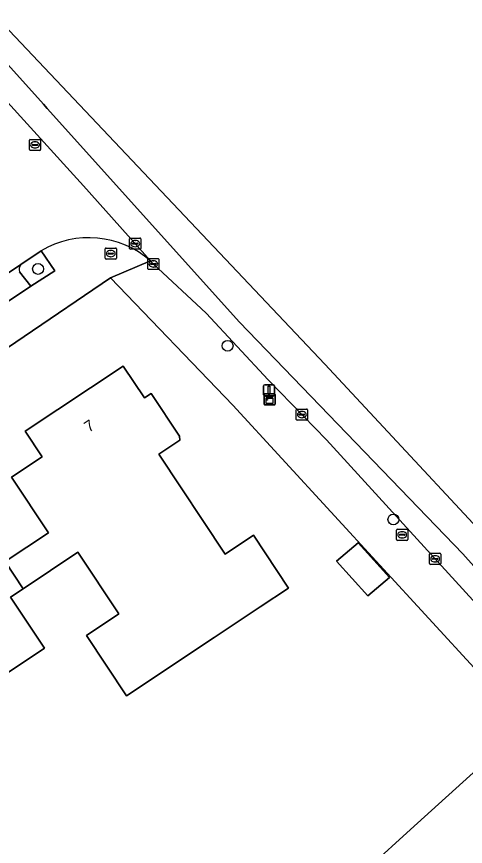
# Model space of a CAD drawing. Extents: x 161347 to 161881, y 382161 to 382804.
# Drawn here: x 161633.8 to 161674.2, y 382587.4 to 382662.1 of the extents above; entities that cross this region are included whole.
import ezdxf

# ---------------------------------------------------------------- set-up
doc = ezdxf.new("R2010")
doc.units = 0
for name, color, linetype in [('IMGEO_Boom', 7, 'Continuous'), ('IMGEO_Brandkraan', 7, 'Continuous'), ('IMGEO_Erf', 7, 'Continuous'), ('IMGEO_Fietspad_gesloten', 7, 'Continuous'), ('IMGEO_Groenvoorziening', 7, 'Continuous'), ('IMGEO_Kast', 7, 'Continuous'), ('IMGEO_Kolk', 7, 'Continuous'), ('IMGEO_Lichtmast', 7, 'Continuous'), ('IMGEO_Muur', 7, 'Continuous'), ('IMGEO_Pand', 7, 'Continuous'), ('IMGEO_Pand_nummerreeks', 7, 'Continuous'), ('IMGEO_Parkeervlak_open', 7, 'Continuous'), ('IMGEO_Rijbaan_lokaal_gesloten', 7, 'Continuous'), ('IMGEO_Rijbaan_lokaal_open', 7, 'Continuous'), ('IMGEO_Rioolput', 7, 'Continuous'), ('IMGEO_Voetpad_open', 7, 'Continuous')]:
    doc.layers.add(name, color=color, linetype=linetype)

msp = doc.modelspace()

# ---------------------------------------------------------------- linework, layer by layer
at = {"layer": 'IMGEO_Boom'}
for centre in [(161635.76, 382639.355), (161652.819, 382632.433), (161667.742, 382616.798)]:
    msp.add_circle(centre, 0.489, dxfattribs=at)
at = {"layer": 'IMGEO_Brandkraan'}
for p, q in [((161641.807, 382640.31), (161641.807, 382641.162)), ((161641.882, 382641.236), (161642.734, 382641.236)), ((161642.066, 382640.73), (161642.066, 382640.742)), ((161642.504, 382640.693), (161642.106, 382640.693)), ((161642.109, 382640.779), (161642.507, 382640.779)), ((161642.295, 382641.016), (161642.32, 382641.016)), ((161642.55, 382640.742), (161642.55, 382640.73)), ((161642.808, 382641.162), (161642.808, 382640.31)), ((161642.734, 382640.236), (161641.882, 382640.236)), ((161642.318, 382640.456), (161642.293, 382640.456))]:
    msp.add_line(p, q, dxfattribs=at)
for points in [[(161641.807, 382640.31), (161641.807, 382641.162)], [(161641.882, 382641.236), (161642.734, 382641.236)], [(161642.808, 382641.162), (161642.808, 382640.31)], [(161642.734, 382640.236), (161641.882, 382640.236)]]:
    msp.add_lwpolyline(points, dxfattribs=at)
for centre, radius, start, end in [((161641.884, 382641.16), 0.0765, 91.55205, 178.44795), ((161641.884, 382641.16), 0.0765, 91.55205, 178.44795), ((161642.106, 382640.739), 0.0403, 85.87752, 175.75265), ((161642.103, 382640.729), 0.0366, 178.93798, 274.71019), ((161642.507, 382640.736), 0.043, 264.86636, 352.45326), ((161642.511, 382640.741), 0.0386, 1.73085, 96.63898), ((161642.732, 382641.16), 0.0765, 1.55205, 88.44795), ((161642.732, 382641.16), 0.0765, 1.55205, 88.44795), ((161641.884, 382640.312), 0.0765, 181.55205, 268.44795), ((161641.884, 382640.312), 0.0765, 181.55205, 268.44795), ((161642.732, 382640.312), 0.0765, 271.55205, 358.44795), ((161642.732, 382640.312), 0.0765, 271.55205, 358.44795)]:
    msp.add_arc(centre, radius, start, end, dxfattribs=at)
for centre, major_axis, ratio, start_param, end_param in [((161642.294, 382640.736), (-0.387, 0.002), 0.722429, 4.712389, 7.853982), ((161642.319, 382640.736), (-0.39, 0.002), 0.717154, 1.570796, 4.712389)]:
    msp.add_ellipse(centre, major_axis=major_axis, ratio=ratio, start_param=start_param, end_param=end_param, dxfattribs=at)
at = {"layer": 'IMGEO_Erf'}
for points in [[(161665.593, 382585.519), (161669.295, 382588.879), (161675.871, 382594.848), (161676.366, 382595.297), (161679.75, 382598.28), (161653.29, 382627.1), (161642.272, 382638.554), (161626.724, 382627.988), (161591.014, 382604.147), (161592.626, 382601.772), (161590.519, 382600.398), (161588.954, 382602.772), (161572.092, 382591.77), (161539.981, 382570.178)], [(161632.808, 382613.004), (161636.704, 382615.596), (161633.373, 382620.601), (161636.145, 382622.446), (161634.617, 382624.742), (161643.428, 382630.605), (161645.338, 382627.735), (161645.942, 382628.137), (161648.492, 382624.305), (161648.516, 382623.924), (161646.628, 382622.668), (161652.605, 382613.685), (161655.144, 382615.375), (161658.302, 382610.63), (161655.763, 382608.94), (161651.601, 382606.171), (161643.724, 382600.93), (161640.118, 382606.349), (161643.044, 382608.296), (161639.351, 382613.846), (161634.428, 382610.57), (161633.287, 382609.811), (161636.354, 382605.203), (161629.995, 382600.972)]]:
    msp.add_lwpolyline(points, dxfattribs=at)
msp.add_lwpolyline([(161662.617, 382613.037), (161664.571, 382614.69), (161667.401, 382611.575), (161665.447, 382609.922)], close=True, dxfattribs=at)
at = {"layer": 'IMGEO_Fietspad_gesloten'}
for points in [[(161706.007, 382577.787), (161673.989, 382613.712), (161653.899, 382634.564), (161636.579, 382653.807), (161636.242, 382654.182), (161624.391, 382667.348), (161616.607, 382676.142), (161601.665, 382692.722), (161589.767, 382705.692), (161577.619, 382719.049), (161575.378, 382721.548)], [(161631.782, 382655.692), (161639.863, 382646.847), (161645.871, 382640.073), (161646.136, 382639.799), (161650.877, 382635.381), (161656.463, 382629.372), (161661.71, 382623.972), (161676.15, 382608.16), (161698.844, 382583.161)]]:
    msp.add_lwpolyline(points, dxfattribs=at)
at = {"layer": 'IMGEO_Groenvoorziening'}
for points in [[(161634.107, 382639.095), (161635.101, 382637.794), (161637.263, 382639.172), (161636.042, 382640.978)], [(161636.042, 382640.978), (161634.21, 382639.745)]]:
    msp.add_lwpolyline(points, dxfattribs=at)
msp.add_arc((161634.687, 382639.336), 0.629, 139.42685, 202.56453, dxfattribs=at)
at = {"layer": 'IMGEO_Kast'}
for p, q in [((161656.109, 382627.188), (161656.109, 382628.029)), ((161656.109, 382628.029), (161656.109, 382627.188)), ((161656.184, 382628.113), (161657.025, 382628.113)), ((161657.025, 382628.113), (161656.184, 382628.113)), ((161657.109, 382628.038), (161657.109, 382627.197)), ((161657.109, 382627.197), (161657.109, 382628.038)), ((161657.034, 382627.113), (161656.193, 382627.113)), ((161656.193, 382627.113), (161657.034, 382627.113))]:
    msp.add_line(p, q, dxfattribs=at)
for points in [[(161656.304, 382627.903), (161656.904, 382627.903), (161656.904, 382627.818), (161656.304, 382627.818), (161656.304, 382627.903)], [(161656.304, 382627.728), (161656.904, 382627.728), (161656.904, 382627.239), (161656.304, 382627.239), (161656.304, 382627.728)]]:
    msp.add_lwpolyline(points, dxfattribs=at)
msp.add_circle((161656.388, 382627.577), 0.0377, dxfattribs=at)
for centre, start, end in [((161656.187, 382628.035), 92.4484, 184.28452), ((161656.187, 382628.035), 92.4484, 184.28452), ((161657.031, 382628.035), 2.4484, 94.28452), ((161657.031, 382628.035), 2.4484, 94.28452), ((161656.187, 382627.191), 182.4484, 274.28452), ((161656.187, 382627.191), 182.4484, 274.28452), ((161657.031, 382627.191), 272.4484, 4.28452), ((161657.031, 382627.191), 272.4484, 4.28452)]:
    msp.add_arc(centre, 0.0779, start, end, dxfattribs=at)
at = {"layer": 'IMGEO_Kolk'}
for p, q in [((161645.635, 382639.373), (161645.635, 382640.225)), ((161645.71, 382640.299), (161646.562, 382640.299)), ((161645.937, 382639.842), (161646.335, 382639.842)), ((161646.123, 382640.079), (161646.148, 382640.079)), ((161646.636, 382640.225), (161646.636, 382639.373)), ((161646.562, 382639.299), (161645.71, 382639.299)), ((161645.894, 382639.793), (161645.894, 382639.805)), ((161646.332, 382639.756), (161645.934, 382639.756)), ((161646.146, 382639.519), (161646.121, 382639.519)), ((161646.378, 382639.805), (161646.378, 382639.793)), ((161659.006, 382625.812), (161659.006, 382626.664)), ((161659.081, 382626.738), (161659.933, 382626.738)), ((161659.494, 382626.518), (161659.519, 382626.518)), ((161660.007, 382626.664), (161660.007, 382625.812)), ((161659.933, 382625.738), (161659.081, 382625.738)), ((161659.265, 382626.232), (161659.265, 382626.244)), ((161659.703, 382626.195), (161659.305, 382626.195)), ((161659.308, 382626.281), (161659.706, 382626.281)), ((161659.517, 382625.958), (161659.492, 382625.958)), ((161659.749, 382626.244), (161659.749, 382626.232)), ((161671, 382612.829), (161671, 382613.681)), ((161671.075, 382613.755), (161671.927, 382613.755)), ((161672.001, 382613.681), (161672.001, 382612.829)), ((161671.259, 382613.249), (161671.259, 382613.261)), ((161671.697, 382613.212), (161671.299, 382613.212)), ((161671.302, 382613.298), (161671.7, 382613.298)), ((161671.511, 382612.975), (161671.486, 382612.975)), ((161671.488, 382613.535), (161671.513, 382613.535)), ((161671.743, 382613.261), (161671.743, 382613.249)), ((161671.927, 382612.755), (161671.075, 382612.755))]:
    msp.add_line(p, q, dxfattribs=at)
for points in [[(161645.635, 382639.373), (161645.635, 382640.225)], [(161645.71, 382640.299), (161646.562, 382640.299)], [(161646.636, 382640.225), (161646.636, 382639.373)], [(161646.562, 382639.299), (161645.71, 382639.299)], [(161659.006, 382625.812), (161659.006, 382626.664)], [(161659.081, 382626.738), (161659.933, 382626.738)], [(161660.007, 382626.664), (161660.007, 382625.812)], [(161659.933, 382625.738), (161659.081, 382625.738)], [(161671, 382612.829), (161671, 382613.681)], [(161671.075, 382613.755), (161671.927, 382613.755)], [(161672.001, 382613.681), (161672.001, 382612.829)], [(161671.927, 382612.755), (161671.075, 382612.755)]]:
    msp.add_lwpolyline(points, dxfattribs=at)
for centre, radius, start, end in [((161645.712, 382640.223), 0.0765, 91.55205, 178.44795), ((161645.712, 382640.223), 0.0765, 91.55205, 178.44795), ((161645.934, 382639.802), 0.0403, 85.87752, 175.75265), ((161646.339, 382639.804), 0.0386, 1.73085, 96.63898), ((161646.56, 382640.223), 0.0765, 1.55205, 88.44795), ((161646.56, 382640.223), 0.0765, 1.55205, 88.44795), ((161645.712, 382639.375), 0.0765, 181.55205, 268.44795), ((161645.712, 382639.375), 0.0765, 181.55205, 268.44795), ((161645.931, 382639.792), 0.0366, 178.93798, 274.71019), ((161646.335, 382639.799), 0.043, 264.86636, 352.45326), ((161646.56, 382639.375), 0.0765, 271.55205, 358.44795), ((161646.56, 382639.375), 0.0765, 271.55205, 358.44795), ((161659.083, 382626.662), 0.0765, 91.55205, 178.44795), ((161659.083, 382626.662), 0.0765, 91.55205, 178.44795), ((161659.931, 382626.662), 0.0765, 1.55205, 88.44795), ((161659.931, 382626.662), 0.0765, 1.55205, 88.44795), ((161659.083, 382625.814), 0.0765, 181.55205, 268.44795), ((161659.083, 382625.814), 0.0765, 181.55205, 268.44795), ((161659.305, 382626.241), 0.0403, 85.87752, 175.75265), ((161659.302, 382626.231), 0.0366, 178.93798, 274.71019), ((161659.706, 382626.238), 0.043, 264.86636, 352.45326), ((161659.71, 382626.243), 0.0386, 1.73085, 96.63898), ((161659.931, 382625.814), 0.0765, 271.55205, 358.44795), ((161659.931, 382625.814), 0.0765, 271.55205, 358.44795), ((161671.077, 382613.679), 0.0765, 91.55205, 178.44795), ((161671.077, 382613.679), 0.0765, 91.55205, 178.44795), ((161671.925, 382613.679), 0.0765, 1.55205, 88.44795), ((161671.925, 382613.679), 0.0765, 1.55205, 88.44795), ((161671.299, 382613.258), 0.0403, 85.87752, 175.75265), ((161671.296, 382613.248), 0.0366, 178.93798, 274.71019), ((161671.7, 382613.255), 0.043, 264.86636, 352.45326), ((161671.704, 382613.26), 0.0386, 1.73085, 96.63898), ((161671.077, 382612.831), 0.0765, 181.55205, 268.44795), ((161671.077, 382612.831), 0.0765, 181.55205, 268.44795), ((161671.925, 382612.831), 0.0765, 271.55205, 358.44795), ((161671.925, 382612.831), 0.0765, 271.55205, 358.44795)]:
    msp.add_arc(centre, radius, start, end, dxfattribs=at)
for centre, major_axis, ratio, start_param, end_param in [((161646.122, 382639.799), (-0.387, 0.002), 0.722429, 4.712389, 7.853982), ((161646.147, 382639.799), (-0.39, 0.002), 0.717154, 1.570796, 4.712389), ((161659.493, 382626.238), (-0.387, 0.002), 0.722429, 4.712389, 7.853982), ((161659.518, 382626.238), (-0.39, 0.002), 0.717154, 1.570796, 4.712389), ((161671.487, 382613.255), (-0.387, 0.002), 0.722429, 4.712389, 7.853982), ((161671.512, 382613.255), (-0.39, 0.002), 0.717154, 1.570796, 4.712389)]:
    msp.add_ellipse(centre, major_axis=major_axis, ratio=ratio, start_param=start_param, end_param=end_param, dxfattribs=at)
at = {"layer": 'IMGEO_Lichtmast'}
for p, q in [((161656.065, 382628.034), (161656.065, 382628.834)), ((161656.065, 382628.834), (161656.065, 382628.034)), ((161656.165, 382628.934), (161656.955, 382628.934)), ((161656.955, 382628.934), (161656.165, 382628.934)), ((161657.055, 382628.834), (161657.055, 382628.034)), ((161657.055, 382628.034), (161657.055, 382628.834)), ((161656.955, 382627.934), (161656.165, 382627.934)), ((161656.165, 382627.934), (161656.955, 382627.934))]:
    msp.add_line(p, q, dxfattribs=at)
msp.add_lwpolyline([(161656.485, 382628.809), (161656.635, 382628.809), (161656.635, 382628.059), (161656.485, 382628.059), (161656.485, 382628.809)], dxfattribs=at)
for centre, start, end in [((161656.165, 382628.834), 90, 180), ((161656.165, 382628.834), 90, 180), ((161656.955, 382628.834), 0, 90), ((161656.955, 382628.834), 360, 90), ((161656.165, 382628.034), 180, 270), ((161656.165, 382628.034), 180, 270), ((161656.955, 382628.034), 270, 0), ((161656.955, 382628.034), 270, 0)]:
    msp.add_arc(centre, 0.1, start, end, dxfattribs=at)
at = {"layer": 'IMGEO_Muur'}
msp.add_lwpolyline([(161653.29, 382627.1), (161679.75, 382598.28)], dxfattribs=at)
at = {"layer": 'IMGEO_Pand'}
for points in [[(161632.808, 382613.004), (161634.428, 382610.57), (161639.351, 382613.846), (161643.044, 382608.296), (161640.118, 382606.349), (161643.724, 382600.93), (161651.601, 382606.171), (161655.763, 382608.94), (161658.302, 382610.63), (161655.144, 382615.375), (161652.605, 382613.685), (161646.628, 382622.668), (161648.516, 382623.924), (161648.492, 382624.305), (161645.942, 382628.137), (161645.338, 382627.735), (161643.428, 382630.605), (161634.617, 382624.742), (161636.145, 382622.446), (161633.373, 382620.601), (161636.704, 382615.596)], [(161662.617, 382613.037), (161665.447, 382609.922), (161667.401, 382611.575), (161664.571, 382614.69)], [(161684.928, 382563.407), (161686.88, 382565.188), (161687.408, 382564.618), (161687.965, 382565.168), (161687.847, 382565.287), (161689.608, 382566.87), (161690.27, 382566.139), (161690.926, 382565.414), (161691.385, 382564.907), (161695.922, 382569.028), (161695.455, 382569.543), (161694.808, 382570.257), (161694.144, 382570.989), (161695.962, 382572.626), (161678.502, 382591.938), (161675.871, 382594.848), (161669.295, 382588.879), (161665.593, 382585.519), (161661.6, 382581.894), (161664.71, 382578.468), (161674.636, 382567.532), (161678.388, 382570.921)]]:
    msp.add_lwpolyline(points, close=True, dxfattribs=at)
msp.add_lwpolyline([(161629.995, 382600.972), (161636.354, 382605.203), (161633.287, 382609.811), (161634.428, 382610.57), (161632.808, 382613.004)], dxfattribs=at)
at = {"layer": 'IMGEO_Parkeervlak_open'}
for points in [[(161634.21, 382639.745), (161623.482, 382632.585)], [(161635.101, 382637.794), (161634.107, 382639.095)], [(161624.045, 382632.438), (161624.388, 382631.946), (161625.023, 382631.053), (161635.101, 382637.794)]]:
    msp.add_lwpolyline(points, dxfattribs=at)
msp.add_arc((161634.687, 382639.336), 0.629, 139.42685, 202.56453, dxfattribs=at)
at = {"layer": 'IMGEO_Rijbaan_lokaal_gesloten'}
for points in [[(161780.196, 382571.153), (161779.525, 382578.285), (161728.827, 382571.874), (161701.238, 382588.176), (161661.586, 382630.771), (161622.627, 382671.947), (161592.087, 382705.487), (161563.602, 382736.77)], [(161575.378, 382721.548), (161577.619, 382719.049), (161589.767, 382705.692), (161601.665, 382692.722), (161616.607, 382676.142), (161624.391, 382667.348), (161636.242, 382654.182), (161636.579, 382653.807), (161653.899, 382634.564), (161673.989, 382613.712), (161706.007, 382577.787), (161705.643, 382575.646), (161721.925, 382567.837)]]:
    msp.add_lwpolyline(points, dxfattribs=at)
at = {"layer": 'IMGEO_Rijbaan_lokaal_open'}
for points in [[(161645.871, 382640.073), (161639.863, 382646.847), (161631.782, 382655.692)], [(161604.234, 382619.763), (161606.677, 382621.365), (161617.031, 382628.308), (161619.464, 382629.933), (161623.482, 382632.585), (161634.21, 382639.745), (161636.042, 382640.978)]]:
    msp.add_lwpolyline(points, dxfattribs=at)
msp.add_arc((161640.338, 382633.811), 8.356, 48.53607, 120.94263, dxfattribs=at)
at = {"layer": 'IMGEO_Rioolput'}
for p, q in [((161634.988, 382650.094), (161634.988, 382650.946)), ((161635.063, 382651.02), (161635.915, 382651.02)), ((161635.247, 382650.514), (161635.247, 382650.526)), ((161635.685, 382650.477), (161635.287, 382650.477)), ((161635.29, 382650.563), (161635.688, 382650.563)), ((161635.476, 382650.8), (161635.501, 382650.8)), ((161635.731, 382650.526), (161635.731, 382650.514)), ((161635.989, 382650.946), (161635.989, 382650.094)), ((161635.915, 382650.02), (161635.063, 382650.02)), ((161635.499, 382650.24), (161635.474, 382650.24)), ((161644.08, 382642.134), (161644.932, 382642.134)), ((161644.005, 382641.208), (161644.005, 382642.06)), ((161644.264, 382641.628), (161644.264, 382641.64)), ((161644.702, 382641.591), (161644.304, 382641.591)), ((161644.307, 382641.677), (161644.705, 382641.677)), ((161644.516, 382641.354), (161644.491, 382641.354)), ((161644.493, 382641.914), (161644.518, 382641.914)), ((161644.748, 382641.64), (161644.748, 382641.628)), ((161645.006, 382642.06), (161645.006, 382641.208)), ((161644.932, 382641.134), (161644.08, 382641.134)), ((161668.103, 382615.92), (161668.955, 382615.92)), ((161668.028, 382614.994), (161668.028, 382615.846)), ((161668.287, 382615.414), (161668.287, 382615.426)), ((161668.725, 382615.377), (161668.327, 382615.377)), ((161668.33, 382615.463), (161668.728, 382615.463)), ((161668.516, 382615.7), (161668.541, 382615.7)), ((161668.771, 382615.426), (161668.771, 382615.414)), ((161669.029, 382615.846), (161669.029, 382614.994)), ((161668.955, 382614.92), (161668.103, 382614.92)), ((161668.539, 382615.14), (161668.514, 382615.14))]:
    msp.add_line(p, q, dxfattribs=at)
for points in [[(161634.988, 382650.094), (161634.988, 382650.946)], [(161635.063, 382651.02), (161635.915, 382651.02)], [(161635.989, 382650.946), (161635.989, 382650.094)], [(161635.915, 382650.02), (161635.063, 382650.02)], [(161644.08, 382642.134), (161644.932, 382642.134)], [(161644.005, 382641.208), (161644.005, 382642.06)], [(161645.006, 382642.06), (161645.006, 382641.208)], [(161644.932, 382641.134), (161644.08, 382641.134)], [(161668.103, 382615.92), (161668.955, 382615.92)], [(161668.028, 382614.994), (161668.028, 382615.846)], [(161669.029, 382615.846), (161669.029, 382614.994)], [(161668.955, 382614.92), (161668.103, 382614.92)]]:
    msp.add_lwpolyline(points, dxfattribs=at)
for centre, radius, start, end in [((161635.065, 382650.944), 0.0765, 91.55205, 178.44795), ((161635.065, 382650.944), 0.0765, 91.55205, 178.44795), ((161635.287, 382650.523), 0.0403, 85.87752, 175.75265), ((161635.284, 382650.513), 0.0366, 178.93798, 274.71019), ((161635.688, 382650.52), 0.043, 264.86636, 352.45326), ((161635.692, 382650.525), 0.0386, 1.73085, 96.63898), ((161635.913, 382650.944), 0.0765, 1.55205, 88.44795), ((161635.913, 382650.944), 0.0765, 1.55205, 88.44795), ((161635.065, 382650.096), 0.0765, 181.55205, 268.44795), ((161635.065, 382650.096), 0.0765, 181.55205, 268.44795), ((161635.913, 382650.096), 0.0765, 271.55205, 358.44795), ((161635.913, 382650.096), 0.0765, 271.55205, 358.44795), ((161644.082, 382642.058), 0.0765, 91.55205, 178.44795), ((161644.082, 382642.058), 0.0765, 91.55205, 178.44795), ((161644.93, 382642.058), 0.0765, 1.55205, 88.44795), ((161644.93, 382642.058), 0.0765, 1.55205, 88.44795), ((161644.304, 382641.637), 0.0403, 85.87752, 175.75265), ((161644.301, 382641.627), 0.0366, 178.93798, 274.71019), ((161644.705, 382641.634), 0.043, 264.86636, 352.45326), ((161644.709, 382641.639), 0.0386, 1.73085, 96.63898), ((161644.082, 382641.21), 0.0765, 181.55205, 268.44795), ((161644.082, 382641.21), 0.0765, 181.55205, 268.44795), ((161644.93, 382641.21), 0.0765, 271.55205, 358.44795), ((161644.93, 382641.21), 0.0765, 271.55205, 358.44795), ((161668.105, 382615.844), 0.0765, 91.55205, 178.44795), ((161668.105, 382615.844), 0.0765, 91.55205, 178.44795), ((161668.953, 382615.844), 0.0765, 1.55205, 88.44795), ((161668.953, 382615.844), 0.0765, 1.55205, 88.44795), ((161668.327, 382615.423), 0.0403, 85.87752, 175.75265), ((161668.324, 382615.413), 0.0366, 178.93798, 274.71019), ((161668.728, 382615.42), 0.043, 264.86636, 352.45326), ((161668.732, 382615.425), 0.0386, 1.73085, 96.63898), ((161668.105, 382614.996), 0.0765, 181.55205, 268.44795), ((161668.105, 382614.996), 0.0765, 181.55205, 268.44795), ((161668.953, 382614.996), 0.0765, 271.55205, 358.44795), ((161668.953, 382614.996), 0.0765, 271.55205, 358.44795)]:
    msp.add_arc(centre, radius, start, end, dxfattribs=at)
for centre, major_axis, ratio, start_param, end_param in [((161635.475, 382650.52), (-0.387, 0.002), 0.722429, 4.712389, 7.853982), ((161635.5, 382650.52), (-0.39, 0.002), 0.717154, 1.570796, 4.712389), ((161644.492, 382641.634), (-0.387, 0.002), 0.722429, 4.712389, 7.853982), ((161644.517, 382641.634), (-0.39, 0.002), 0.717154, 1.570796, 4.712389), ((161668.515, 382615.42), (-0.387, 0.002), 0.722429, 4.712389, 7.853982), ((161668.54, 382615.42), (-0.39, 0.002), 0.717154, 1.570796, 4.712389)]:
    msp.add_ellipse(centre, major_axis=major_axis, ratio=ratio, start_param=start_param, end_param=end_param, dxfattribs=at)
at = {"layer": 'IMGEO_Voetpad_open'}
for points in [[(161636.042, 382640.978), (161637.263, 382639.172), (161635.101, 382637.794), (161625.023, 382631.053), (161624.388, 382631.946), (161620.048, 382629.035), (161620.647, 382628.172), (161617.655, 382626.128), (161608.366, 382619.905), (161604.861, 382617.547), (161590.935, 382608.278), (161587.772, 382606.172), (161587.144, 382607.09), (161574.859, 382598.875), (161575.536, 382597.897), (161570.33, 382594.467), (161567.696, 382592.692), (161553.267, 382582.995), (161550.455, 382581.099), (161540.9, 382574.692), (161538.305, 382572.954), (161537.081, 382574.722), (161535.802, 382573.856), (161531.835, 382571.172)], [(161539.981, 382570.178), (161572.092, 382591.77), (161588.954, 382602.772), (161591.014, 382604.147), (161626.724, 382627.988), (161642.272, 382638.554), (161645.871, 382640.073)], [(161661.71, 382623.972), (161656.463, 382629.372), (161650.877, 382635.381), (161646.136, 382639.799), (161645.871, 382640.073), (161642.272, 382638.554), (161653.29, 382627.1), (161679.75, 382598.28), (161682.518, 382595.225), (161696.997, 382579.273), (161702.259, 382573.539), (161707.903, 382567.394)], [(161705.643, 382575.646), (161704.285, 382577.171), (161698.844, 382583.161), (161676.15, 382608.16), (161661.71, 382623.972)]]:
    msp.add_lwpolyline(points, dxfattribs=at)
msp.add_arc((161640.338, 382633.811), 8.356, 48.53607, 120.94263, dxfattribs=at)

# ---------------------------------------------------------------- texts
at = {"layer": 'IMGEO_Pand_nummerreeks'}
msp.add_text('7', height=1, rotation=33.64052, dxfattribs=at).set_placement((161640.337, 382624.608))

doc.saveas('drawing.dxf')
